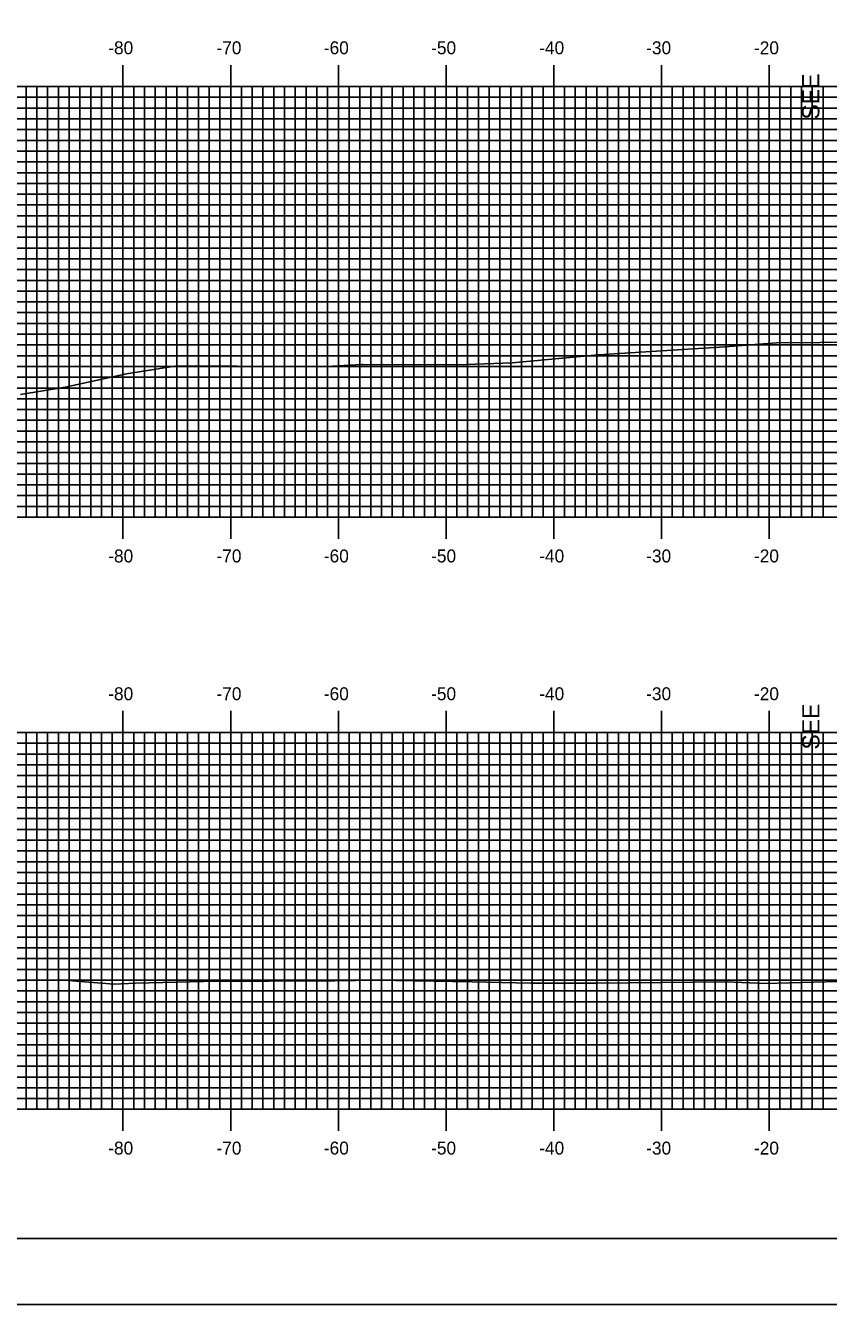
# Model space of a CAD drawing. Extents: x 852936 to 853279, y 364366 to 364586.
# Drawn here: x 853012.6 to 853087.2, y 364365.7 to 364484.5 of the extents above; entities that cross this region are included whole.
import ezdxf

# ---------------------------------------------------------------- set-up
doc = ezdxf.new("R2010")
doc.units = 0
for name, color, linetype in [('ANNOTATION', 7, 'Continuous'), ('BORDER', 7, 'Continuous'), ('H_V ANNOTATION', 7, 'Continuous'), ('MAJOR', 7, 'Continuous'), ('MINOR', 7, 'Continuous'), ('PLOT BOUNDARY', 7, 'Continuous'), ('S_Roadway_Centerline', 7, 'Continuous')]:
    doc.layers.add(name, color=color, linetype=linetype)

msp = doc.modelspace()

# ---------------------------------------------------------------- linework, layer by layer
at = {"layer": 'BORDER'}
msp.add_lwpolyline([(852952.09, 364371.79), (853272.09, 364371.79), (853272.09, 364581.79), (852952.09, 364581.79)], close=True, dxfattribs=at)
at = {"layer": 'MAJOR'}
for p, q in [((853021.69, 364480.79), (853021.69, 364478.79)), ((853031.69, 364480.79), (853031.69, 364478.79)), ((853041.69, 364480.79), (853041.69, 364478.79)), ((853051.69, 364480.79), (853051.69, 364478.79)), ((853061.69, 364480.79), (853061.69, 364478.79)), ((853071.69, 364480.79), (853071.69, 364478.79)), ((853081.69, 364480.79), (853081.69, 364478.79)), ((852961.69, 364478.79), (853241.69, 364478.79)), ((852961.69, 364478.79), (853241.69, 364478.79)), ((853021.69, 364438.79), (853021.69, 364478.79)), ((853031.69, 364438.79), (853031.69, 364478.79)), ((853041.69, 364438.79), (853041.69, 364478.79)), ((853051.69, 364438.79), (853051.69, 364478.79)), ((853061.69, 364438.79), (853061.69, 364478.79)), ((853071.69, 364438.79), (853071.69, 364478.79)), ((853081.69, 364438.79), (853081.69, 364478.79)), ((852961.69, 364473.79), (853241.69, 364473.79)), ((852961.69, 364468.79), (853241.69, 364468.79)), ((852961.69, 364463.79), (853241.69, 364463.79)), ((852961.69, 364458.79), (853241.69, 364458.79)), ((852961.69, 364453.79), (853241.69, 364453.79)), ((852961.69, 364448.79), (853241.69, 364448.79)), ((852961.69, 364443.79), (853241.69, 364443.79)), ((852961.69, 364438.79), (853241.69, 364438.79)), ((852961.69, 364438.79), (853241.69, 364438.79)), ((853021.69, 364436.78), (853021.69, 364438.79)), ((853031.69, 364436.78), (853031.69, 364438.79)), ((853041.69, 364436.78), (853041.69, 364438.79)), ((853051.69, 364436.78), (853051.69, 364438.79)), ((853061.69, 364436.78), (853061.69, 364438.79)), ((853071.69, 364436.78), (853071.69, 364438.79)), ((853081.69, 364436.78), (853081.69, 364438.79)), ((853021.69, 364420.79), (853021.69, 364418.79)), ((853031.69, 364420.79), (853031.69, 364418.79)), ((853041.69, 364420.79), (853041.69, 364418.79)), ((853051.69, 364420.79), (853051.69, 364418.79)), ((853061.69, 364420.79), (853061.69, 364418.79)), ((853071.69, 364420.79), (853071.69, 364418.79)), ((853081.69, 364420.79), (853081.69, 364418.79)), ((852961.69, 364418.79), (853241.69, 364418.79)), ((852961.69, 364418.79), (853241.69, 364418.79)), ((853021.69, 364383.79), (853021.69, 364418.79)), ((853031.69, 364383.79), (853031.69, 364418.79)), ((853041.69, 364383.79), (853041.69, 364418.79)), ((853051.69, 364383.79), (853051.69, 364418.79)), ((853061.69, 364383.79), (853061.69, 364418.79)), ((853071.69, 364383.79), (853071.69, 364418.79)), ((853081.69, 364383.79), (853081.69, 364418.79)), ((852961.69, 364413.79), (853241.69, 364413.79)), ((852961.69, 364408.79), (853241.69, 364408.79)), ((852961.69, 364403.79), (853241.69, 364403.79)), ((852961.69, 364398.79), (853241.69, 364398.79)), ((852961.69, 364393.79), (853241.69, 364393.79)), ((852961.69, 364388.79), (853241.69, 364388.79)), ((852961.69, 364383.79), (853241.69, 364383.79)), ((852961.69, 364383.79), (853241.69, 364383.79)), ((853021.69, 364381.78), (853021.69, 364383.79)), ((853031.69, 364381.78), (853031.69, 364383.79)), ((853041.69, 364381.78), (853041.69, 364383.79)), ((853051.69, 364381.78), (853051.69, 364383.79)), ((853061.69, 364381.78), (853061.69, 364383.79)), ((853071.69, 364381.78), (853071.69, 364383.79)), ((853081.69, 364381.78), (853081.69, 364383.79))]:
    msp.add_line(p, q, dxfattribs=at)
at = {"layer": 'MINOR'}
for p, q in [((853012.69, 364438.79), (853012.69, 364478.79)), ((853013.69, 364438.79), (853013.69, 364478.79)), ((853014.69, 364438.79), (853014.69, 364478.79)), ((853015.69, 364438.79), (853015.69, 364478.79)), ((853016.69, 364438.79), (853016.69, 364478.79)), ((853017.69, 364438.79), (853017.69, 364478.79)), ((853018.69, 364438.79), (853018.69, 364478.79)), ((853019.69, 364438.79), (853019.69, 364478.79)), ((853020.69, 364438.79), (853020.69, 364478.79)), ((853022.69, 364438.79), (853022.69, 364478.79)), ((853023.69, 364438.79), (853023.69, 364478.79)), ((853024.69, 364438.79), (853024.69, 364478.79)), ((853025.69, 364438.79), (853025.69, 364478.79)), ((853026.69, 364438.79), (853026.69, 364478.79)), ((853027.69, 364438.79), (853027.69, 364478.79)), ((853028.69, 364438.79), (853028.69, 364478.79)), ((853029.69, 364438.79), (853029.69, 364478.79)), ((853030.69, 364438.79), (853030.69, 364478.79)), ((853032.69, 364438.79), (853032.69, 364478.79)), ((853033.69, 364438.79), (853033.69, 364478.79)), ((853034.69, 364438.79), (853034.69, 364478.79)), ((853035.69, 364438.79), (853035.69, 364478.79)), ((853036.69, 364438.79), (853036.69, 364478.79)), ((853037.69, 364438.79), (853037.69, 364478.79)), ((853038.69, 364438.79), (853038.69, 364478.79)), ((853039.69, 364438.79), (853039.69, 364478.79)), ((853040.69, 364438.79), (853040.69, 364478.79)), ((853042.69, 364438.79), (853042.69, 364478.79)), ((853043.69, 364438.79), (853043.69, 364478.79)), ((853044.69, 364438.79), (853044.69, 364478.79)), ((853045.69, 364438.79), (853045.69, 364478.79)), ((853046.69, 364438.79), (853046.69, 364478.79)), ((853047.69, 364438.79), (853047.69, 364478.79)), ((853048.69, 364438.79), (853048.69, 364478.79)), ((853049.69, 364438.79), (853049.69, 364478.79)), ((853050.69, 364438.79), (853050.69, 364478.79)), ((853052.69, 364438.79), (853052.69, 364478.79)), ((853053.69, 364438.79), (853053.69, 364478.79)), ((853054.69, 364438.79), (853054.69, 364478.79)), ((853055.69, 364438.79), (853055.69, 364478.79)), ((853056.69, 364438.79), (853056.69, 364478.79)), ((853057.69, 364438.79), (853057.69, 364478.79)), ((853058.69, 364438.79), (853058.69, 364478.79)), ((853059.69, 364438.79), (853059.69, 364478.79)), ((853060.69, 364438.79), (853060.69, 364478.79)), ((853062.69, 364438.79), (853062.69, 364478.79)), ((853063.69, 364438.79), (853063.69, 364478.79)), ((853064.69, 364438.79), (853064.69, 364478.79)), ((853065.69, 364438.79), (853065.69, 364478.79)), ((853066.69, 364438.79), (853066.69, 364478.79)), ((853067.69, 364438.79), (853067.69, 364478.79)), ((853068.69, 364438.79), (853068.69, 364478.79)), ((853069.69, 364438.79), (853069.69, 364478.79)), ((853070.69, 364438.79), (853070.69, 364478.79)), ((853072.69, 364438.79), (853072.69, 364478.79)), ((853073.69, 364438.79), (853073.69, 364478.79)), ((853074.69, 364438.79), (853074.69, 364478.79)), ((853075.69, 364438.79), (853075.69, 364478.79)), ((853076.69, 364438.79), (853076.69, 364478.79)), ((853077.69, 364438.79), (853077.69, 364478.79)), ((853078.69, 364438.79), (853078.69, 364478.79)), ((853079.69, 364438.79), (853079.69, 364478.79)), ((853080.69, 364438.79), (853080.69, 364478.79)), ((853082.69, 364438.79), (853082.69, 364478.79)), ((853083.69, 364438.79), (853083.69, 364478.79)), ((853084.69, 364438.79), (853084.69, 364478.79)), ((853085.69, 364438.79), (853085.69, 364478.79)), ((853086.69, 364438.79), (853086.69, 364478.79)), ((852961.69, 364477.79), (853241.69, 364477.79)), ((852961.69, 364476.79), (853241.69, 364476.79)), ((852961.69, 364475.79), (853241.69, 364475.79)), ((852961.69, 364474.79), (853241.69, 364474.79)), ((852961.69, 364472.79), (853241.69, 364472.79)), ((852961.69, 364471.79), (853241.69, 364471.79)), ((852961.69, 364470.79), (853241.69, 364470.79)), ((852961.69, 364469.79), (853241.69, 364469.79)), ((852961.69, 364467.79), (853241.69, 364467.79)), ((852961.69, 364466.79), (853241.69, 364466.79)), ((852961.69, 364465.79), (853241.69, 364465.79)), ((852961.69, 364464.79), (853241.69, 364464.79)), ((852961.69, 364462.79), (853241.69, 364462.79)), ((852961.69, 364461.79), (853241.69, 364461.79)), ((852961.69, 364460.79), (853241.69, 364460.79)), ((852961.69, 364459.79), (853241.69, 364459.79)), ((852961.69, 364457.79), (853241.69, 364457.79)), ((852961.69, 364456.79), (853241.69, 364456.79)), ((852961.69, 364455.79), (853241.69, 364455.79)), ((852961.69, 364454.79), (853241.69, 364454.79)), ((852961.69, 364452.79), (853241.69, 364452.79)), ((852961.69, 364451.79), (853241.69, 364451.79)), ((852961.69, 364450.79), (853241.69, 364450.79)), ((852961.69, 364449.79), (853241.69, 364449.79)), ((852961.69, 364447.79), (853241.69, 364447.79)), ((852961.69, 364446.79), (853241.69, 364446.79)), ((852961.69, 364445.79), (853241.69, 364445.79)), ((852961.69, 364444.79), (853241.69, 364444.79)), ((852961.69, 364442.79), (853241.69, 364442.79)), ((852961.69, 364441.79), (853241.69, 364441.79)), ((852961.69, 364440.79), (853241.69, 364440.79)), ((852961.69, 364439.79), (853241.69, 364439.79)), ((852961.69, 364417.79), (853241.69, 364417.79)), ((853012.69, 364383.79), (853012.69, 364418.79)), ((853013.69, 364383.79), (853013.69, 364418.79)), ((853014.69, 364383.79), (853014.69, 364418.79)), ((853015.69, 364383.79), (853015.69, 364418.79)), ((853016.69, 364383.79), (853016.69, 364418.79)), ((853017.69, 364383.79), (853017.69, 364418.79)), ((853018.69, 364383.79), (853018.69, 364418.79)), ((853019.69, 364383.79), (853019.69, 364418.79)), ((853020.69, 364383.79), (853020.69, 364418.79)), ((853022.69, 364383.79), (853022.69, 364418.79)), ((853023.69, 364383.79), (853023.69, 364418.79)), ((853024.69, 364383.79), (853024.69, 364418.79)), ((853025.69, 364383.79), (853025.69, 364418.79)), ((853026.69, 364383.79), (853026.69, 364418.79)), ((853027.69, 364383.79), (853027.69, 364418.79)), ((853028.69, 364383.79), (853028.69, 364418.79)), ((853029.69, 364383.79), (853029.69, 364418.79)), ((853030.69, 364383.79), (853030.69, 364418.79)), ((853032.69, 364383.79), (853032.69, 364418.79)), ((853033.69, 364383.79), (853033.69, 364418.79)), ((853034.69, 364383.79), (853034.69, 364418.79)), ((853035.69, 364383.79), (853035.69, 364418.79)), ((853036.69, 364383.79), (853036.69, 364418.79)), ((853037.69, 364383.79), (853037.69, 364418.79)), ((853038.69, 364383.79), (853038.69, 364418.79)), ((853039.69, 364383.79), (853039.69, 364418.79)), ((853040.69, 364383.79), (853040.69, 364418.79)), ((853042.69, 364383.79), (853042.69, 364418.79)), ((853043.69, 364383.79), (853043.69, 364418.79)), ((853044.69, 364383.79), (853044.69, 364418.79)), ((853045.69, 364383.79), (853045.69, 364418.79)), ((853046.69, 364383.79), (853046.69, 364418.79)), ((853047.69, 364383.79), (853047.69, 364418.79)), ((853048.69, 364383.79), (853048.69, 364418.79)), ((853049.69, 364383.79), (853049.69, 364418.79)), ((853050.69, 364383.79), (853050.69, 364418.79)), ((853052.69, 364383.79), (853052.69, 364418.79)), ((853053.69, 364383.79), (853053.69, 364418.79)), ((853054.69, 364383.79), (853054.69, 364418.79)), ((853055.69, 364383.79), (853055.69, 364418.79)), ((853056.69, 364383.79), (853056.69, 364418.79)), ((853057.69, 364383.79), (853057.69, 364418.79)), ((853058.69, 364383.79), (853058.69, 364418.79)), ((853059.69, 364383.79), (853059.69, 364418.79)), ((853060.69, 364383.79), (853060.69, 364418.79)), ((853062.69, 364383.79), (853062.69, 364418.79)), ((853063.69, 364383.79), (853063.69, 364418.79)), ((853064.69, 364383.79), (853064.69, 364418.79)), ((853065.69, 364383.79), (853065.69, 364418.79)), ((853066.69, 364383.79), (853066.69, 364418.79)), ((853067.69, 364383.79), (853067.69, 364418.79)), ((853068.69, 364383.79), (853068.69, 364418.79)), ((853069.69, 364383.79), (853069.69, 364418.79)), ((853070.69, 364383.79), (853070.69, 364418.79)), ((853072.69, 364383.79), (853072.69, 364418.79)), ((853073.69, 364383.79), (853073.69, 364418.79)), ((853074.69, 364383.79), (853074.69, 364418.79)), ((853075.69, 364383.79), (853075.69, 364418.79)), ((853076.69, 364383.79), (853076.69, 364418.79)), ((853077.69, 364383.79), (853077.69, 364418.79)), ((853078.69, 364383.79), (853078.69, 364418.79)), ((853079.69, 364383.79), (853079.69, 364418.79)), ((853080.69, 364383.79), (853080.69, 364418.79)), ((853082.69, 364383.79), (853082.69, 364418.79)), ((853083.69, 364383.79), (853083.69, 364418.79)), ((853084.69, 364383.79), (853084.69, 364418.79)), ((853085.69, 364383.79), (853085.69, 364418.79)), ((853086.69, 364383.79), (853086.69, 364418.79)), ((852961.69, 364416.79), (853241.69, 364416.79)), ((852961.69, 364415.79), (853241.69, 364415.79)), ((852961.69, 364414.79), (853241.69, 364414.79)), ((852961.69, 364412.79), (853241.69, 364412.79)), ((852961.69, 364411.79), (853241.69, 364411.79)), ((852961.69, 364410.79), (853241.69, 364410.79)), ((852961.69, 364409.79), (853241.69, 364409.79)), ((852961.69, 364407.79), (853241.69, 364407.79)), ((852961.69, 364406.79), (853241.69, 364406.79)), ((852961.69, 364405.79), (853241.69, 364405.79)), ((852961.69, 364404.79), (853241.69, 364404.79)), ((852961.69, 364402.79), (853241.69, 364402.79)), ((852961.69, 364401.79), (853241.69, 364401.79)), ((852961.69, 364400.79), (853241.69, 364400.79)), ((852961.69, 364399.79), (853241.69, 364399.79)), ((852961.69, 364397.79), (853241.69, 364397.79)), ((852961.69, 364396.79), (853241.69, 364396.79)), ((852961.69, 364395.79), (853241.69, 364395.79)), ((852961.69, 364394.79), (853241.69, 364394.79)), ((852961.69, 364392.79), (853241.69, 364392.79)), ((852961.69, 364391.79), (853241.69, 364391.79)), ((852961.69, 364390.79), (853241.69, 364390.79)), ((852961.69, 364389.79), (853241.69, 364389.79)), ((852961.69, 364387.79), (853241.69, 364387.79)), ((852961.69, 364386.79), (853241.69, 364386.79)), ((852961.69, 364385.79), (853241.69, 364385.79)), ((852961.69, 364384.79), (853241.69, 364384.79))]:
    msp.add_line(p, q, dxfattribs=at)
at = {"layer": 'PLOT BOUNDARY'}
msp.add_lwpolyline([(852935.9, 364365.67), (853275.9, 364365.67), (853275.9, 364585.67), (852935.9, 364585.67)], close=True, dxfattribs=at)
at = {"layer": 'S_Roadway_Centerline'}
for points in [[(853012.17, 364450.18), (853016.32, 364450.88), (853022.02, 364452.12), (853026.49, 364452.82), (853028.4, 364452.85), (853040.06, 364452.76), (853043.85, 364452.96), (853043.96, 364452.96), (853052.69, 364452.93), (853057.82, 364453.14), (853065.84, 364453.88), (853077.58, 364454.62), (853082.38, 364454.99), (853090.46, 364455.06)], [(852961.69, 364394.18), (852965.46, 364394.24), (852966.99, 364394.32), (852967.65, 364394.31), (852970.38, 364394.49), (852982.86, 364395.05), (852988, 364395.28), (852993.13, 364395.77), (853003.97, 364395.86), (853006.46, 364395.67), (853015.84, 364395.83), (853020.86, 364395.43), (853022.84, 364395.52), (853029.16, 364395.65), (853041.36, 364395.71), (853045.19, 364395.8), (853054.1, 364395.63), (853059.55, 364395.51), (853065.7, 364395.52), (853077.73, 364395.63), (853081.31, 364395.49), (853092.62, 364395.78)]]:
    msp.add_lwpolyline(points, dxfattribs=at)

# ---------------------------------------------------------------- texts
at = {"layer": 'ANNOTATION'}
for p in [(853086.35, 364475.72), (853086.36, 364417.2)]:
    msp.add_text('SEE', height=1.6, rotation=90, dxfattribs=at).set_placement(p)
at = {"layer": 'H_V ANNOTATION'}
for s, p in [('-80', (853020.32, 364481.79)), ('-70', (853030.37, 364481.79)), ('-60', (853040.34, 364481.79)), ('-50', (853050.3, 364481.79)), ('-40', (853060.34, 364481.79)), ('-30', (853070.27, 364481.79)), ('-20', (853080.28, 364481.79)), ('-80', (853020.32, 364434.59)), ('-70', (853030.37, 364434.59)), ('-60', (853040.34, 364434.59)), ('-50', (853050.3, 364434.59)), ('-40', (853060.34, 364434.59)), ('-30', (853070.27, 364434.59)), ('-20', (853080.28, 364434.59)), ('-80', (853020.32, 364421.79)), ('-70', (853030.37, 364421.79)), ('-60', (853040.34, 364421.79)), ('-50', (853050.3, 364421.79)), ('-40', (853060.34, 364421.79)), ('-30', (853070.27, 364421.79)), ('-20', (853080.28, 364421.79)), ('-80', (853020.32, 364379.59)), ('-70', (853030.37, 364379.59)), ('-60', (853040.34, 364379.59)), ('-50', (853050.3, 364379.59)), ('-40', (853060.34, 364379.59)), ('-30', (853070.27, 364379.59)), ('-20', (853080.28, 364379.59))]:
    msp.add_text(s, height=1.2, dxfattribs=at).set_placement(p)

doc.saveas('drawing.dxf')
